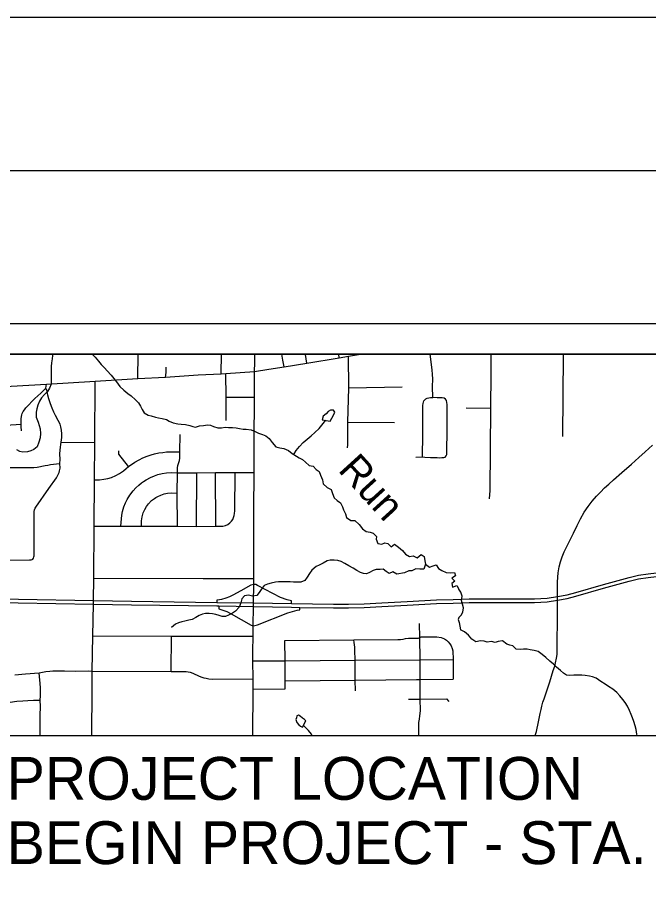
# Model space of a CAD drawing. Extents: x 0 to 34, y -5 to 22.
# Drawn here: x 5.836 to 7.898, y 19.168 to 22 of the extents above; entities that cross this region are included whole.
import ezdxf

# ---------------------------------------------------------------- set-up
doc = ezdxf.new("R2010")
doc.units = 0
for name, color, linetype in [('GM_X_City_Street', 7, 'Continuous'), ('GM_X_County_Road', 7, 'Continuous'), ('GM_X_Interchange_Ramps', 7, 'Continuous'), ('GM_X_Interstate_Route', 7, 'Continuous'), ('GM_X_Minor_Lake', 7, 'Continuous'), ('GM_X_Minor_River', 7, 'Continuous'), ('GM_X_Minor_River_Text', 7, 'Continuous'), ('GM_X_State_Route', 7, 'Continuous'), ('GM_X_US_Route', 7, 'Continuous'), ('SC_Scratch2', 7, 'Continuous'), ('SH_Border', 7, 'Continuous'), ('SH_Cut_Line', 7, 'Continuous'), ('SH_Data', 7, 'Continuous'), ('SH_Text', 7, 'Continuous')]:
    doc.layers.add(name, color=color, linetype=linetype)

msp = doc.modelspace()

# ---------------------------------------------------------------- linework, layer by layer
at = {"layer": 'GM_X_City_Street'}
for p, q in [((6.2296, 20.8205), (6.2299, 20.9)), ((6.5009, 20.8363), (6.5026, 20.9)), ((6.8873, 20.8885), (6.8858, 20.9)), ((6.918, 20.7901), (7.093, 20.7932)), ((6.5182, 20.7598), (6.6101, 20.7598)), ((7.3021, 20.7251), (7.3821, 20.7236)), ((6.9156, 20.6784), (7.0674, 20.6772)), ((5.9792, 20.6132), (6.0887, 20.6113)), ((6.4209, 20.3378), (6.4219, 20.5131)), ((6.4839, 20.3383), (6.4832, 20.5135)), ((6.338, 19.8642), (6.339, 19.9798))]:
    msp.add_line(p, q, dxfattribs=at)
for points in [[(6.7072, 20.8588), (6.7034, 20.8804), (6.6999, 20.9)], [(6.7813, 20.8707), (6.7773, 20.8986), (6.7771, 20.9)], [(6.914, 20.5948), (6.9154, 20.6038), (6.9156, 20.6784), (6.918, 20.7901), (6.9175, 20.8934)], [(7.1925, 20.7586), (7.1922, 20.7949), (7.1927, 20.8188), (7.192, 20.8354), (7.191, 20.8479), (7.1863, 20.8834), (7.1842, 20.9)], [(7.3781, 20.4278), (7.3798, 20.4553), (7.3821, 20.7236), (7.3833, 20.8363), (7.384, 20.9)], [(7.6171, 20.631), (7.6199, 20.8962), (7.6199, 20.9)], [(6.3192, 20.8256), (6.3203, 20.8316), (6.3214, 20.8411), (6.3219, 20.8489), (6.3222, 20.8579)], [(6.5178, 20.6838), (6.5182, 20.7598), (6.5169, 20.8369)], [(5.8495, 20.6502), (5.8483, 20.6642), (5.8478, 20.6717), (5.8481, 20.6812), (5.8481, 20.689), (5.849, 20.6968), (5.8499, 20.702), (5.8511, 20.7063), (5.8549, 20.7127), (5.8585, 20.7181), (5.8638, 20.7251), (5.8926, 20.7549), (5.912, 20.7733), (5.9287, 20.7894)], [(5.8862, 20.2308), (5.8885, 20.2343), (5.8895, 20.2381), (5.8902, 20.2419), (5.89, 20.3733), (5.89, 20.3819), (5.8904, 20.3868), (5.8914, 20.3916), (5.8942, 20.397), (5.8964, 20.4006), (5.9383, 20.4612), (5.9631, 20.4962), (5.9691, 20.5069), (5.9721, 20.5133), (5.9738, 20.5197), (5.975, 20.5277), (5.9747, 20.5434), (5.9752, 20.5566), (5.9747, 20.5744), (5.9755, 20.5872), (5.9764, 20.5964), (5.9776, 20.6047), (5.9792, 20.6132), (5.9814, 20.6279), (5.9814, 20.6402), (5.9802, 20.6518), (5.9778, 20.663), (5.975, 20.6713), (5.9691, 20.6833), (5.9598, 20.6994), (5.9549, 20.711), (5.9494, 20.7234), (5.9435, 20.7385), (5.9385, 20.7544), (5.9347, 20.7667), (5.9328, 20.779), (5.9287, 20.7894), (5.9309, 20.8026)], [(6.0784, 19.6552), (6.0804, 19.804), (6.0799, 19.8656), (6.0827, 19.9809), (6.084, 20.0843), (6.0838, 20.0963), (6.0851, 20.169), (6.0863, 20.339), (6.0879, 20.4896), (6.0887, 20.6113), (6.09, 20.8115)], [(7.1588, 20.5647), (7.1598, 20.6381), (7.1603, 20.7001), (7.1603, 20.7264), (7.16, 20.7328), (7.161, 20.7387), (7.1624, 20.7437), (7.164, 20.7482), (7.1667, 20.7516), (7.1702, 20.7546), (7.1745, 20.7567), (7.1801, 20.7579), (7.1858, 20.7586), (7.1925, 20.7586)], [(7.233, 20.5642), (7.2365, 20.5678), (7.2384, 20.5725), (7.2386, 20.5794), (7.2389, 20.5993), (7.2393, 20.6338), (7.2398, 20.7357), (7.2389, 20.7425), (7.2372, 20.7487), (7.2339, 20.753), (7.2294, 20.756), (7.2237, 20.7575), (7.2152, 20.7575), (7.2074, 20.7579), (7.1925, 20.7586)], [(5.7315, 20.6703), (5.7334, 20.6677), (5.7363, 20.6658), (5.7403, 20.6649), (5.7465, 20.6651), (5.8478, 20.6717)], [(6.3586, 20.3383), (6.3579, 20.4465), (6.3586, 20.5131), (6.3584, 20.5225), (6.3593, 20.5292), (6.3603, 20.537), (6.3619, 20.5427), (6.365, 20.5526), (6.3664, 20.5604), (6.3667, 20.5675), (6.3669, 20.5813), (6.3679, 20.6376)], [(7.5274, 19.6552), (7.5311, 19.6683), (7.5382, 19.6994), (7.5434, 19.7268), (7.5465, 19.7399), (7.5489, 19.7508), (7.5524, 19.764), (7.5562, 19.7747), (7.5752, 19.8303), (7.5865, 19.8673), (7.591, 19.881), (7.5941, 19.8928), (7.5974, 19.9073), (7.5991, 19.9196), (7.5995, 19.9336), (7.5993, 19.9568), (7.6005, 20.0347), (7.6001, 20.0968), (7.6001, 20.1092), (7.6001, 20.1568), (7.6024, 20.1865), (7.6055, 20.2061), (7.6095, 20.2223), (7.6154, 20.2388), (7.6225, 20.2545), (7.6303, 20.272), (7.6396, 20.2895), (7.6521, 20.3158), (7.6644, 20.3407), (7.6758, 20.3629), (7.6876, 20.384), (7.7, 20.4025), (7.7137, 20.4207), (7.7274, 20.4366), (7.7405, 20.4501), (7.7542, 20.4633), (7.7682, 20.4756), (7.7836, 20.4899), (7.8108, 20.5135), (7.8418, 20.5412), (7.8662, 20.563), (7.8868, 20.5815), (7.9105, 20.6028)], [(6.0879, 20.4896), (6.1036, 20.4901), (6.118, 20.4915), (6.1313, 20.4939), (6.1429, 20.4974), (6.1571, 20.5036), (6.1696, 20.5109), (6.1824, 20.5195), (6.1912, 20.5273), (6.1985, 20.5334), (6.2197, 20.548), (6.2334, 20.5555), (6.2458, 20.5619), (6.2594, 20.5666), (6.2724, 20.5711), (6.284, 20.5744), (6.2982, 20.5775), (6.3113, 20.5796), (6.3226, 20.5808), (6.3316, 20.5815), (6.3423, 20.5817), (6.3669, 20.5813)], [(6.1985, 20.5334), (6.1666, 20.5739), (6.1675, 20.5846)], [(7.1373, 20.5637), (7.1588, 20.5647), (7.1671, 20.5637), (7.1851, 20.563), (7.2074, 20.5626), (7.215, 20.5621), (7.2218, 20.5623), (7.2287, 20.5628), (7.233, 20.5642)], [(5.6465, 20.4906), (5.6858, 20.4896), (5.6936, 20.4903), (5.7005, 20.4917), (5.706, 20.4934), (5.7244, 20.5031), (5.7607, 20.5235), (5.7663, 20.5266), (5.7711, 20.5282), (5.7751, 20.5287), (5.7787, 20.5292), (5.7931, 20.5296), (5.8765, 20.5299), (5.8895, 20.5301), (5.9001, 20.5314), (5.9267, 20.5365), (5.9347, 20.5372), (5.9437, 20.5398), (5.9539, 20.541), (5.9634, 20.542), (5.9747, 20.5434)], [(6.0863, 20.339), (6.1741, 20.3385), (6.2416, 20.3383), (6.3586, 20.3383), (6.4209, 20.3378), (6.4839, 20.3383), (6.4972, 20.3381), (6.5073, 20.339), (6.5154, 20.3409), (6.523, 20.3444), (6.5298, 20.3492), (6.5353, 20.3549), (6.5391, 20.3603), (6.5419, 20.3672), (6.5443, 20.3738), (6.5455, 20.3802), (6.5459, 20.3887), (6.5467, 20.5133)], [(6.1741, 20.3385), (6.1753, 20.3627), (6.1768, 20.3741), (6.1796, 20.3868), (6.1836, 20.4013), (6.1891, 20.4145), (6.1943, 20.4252), (6.2033, 20.4401), (6.2139, 20.4539), (6.2222, 20.4636), (6.2322, 20.4728), (6.2409, 20.4799), (6.2478, 20.4849), (6.2563, 20.4903), (6.2705, 20.4979), (6.2833, 20.5034), (6.294, 20.5069), (6.3087, 20.5107), (6.3233, 20.5126), (6.3378, 20.5138), (6.3586, 20.5131), (6.4219, 20.5131), (6.4832, 20.5135), (6.5467, 20.5133), (6.6089, 20.514)], [(6.2416, 20.3383), (6.2414, 20.3565), (6.2435, 20.3688), (6.2468, 20.3816), (6.2523, 20.3935), (6.2575, 20.4029), (6.2644, 20.4117), (6.2743, 20.4219), (6.2836, 20.4292), (6.2883, 20.4321), (6.2942, 20.4354), (6.3042, 20.4399), (6.3153, 20.4437), (6.3262, 20.4458), (6.338, 20.447), (6.3579, 20.4465)], [(5.6498, 20.2289), (5.6517, 20.2279), (5.6553, 20.2277), (5.6588, 20.2275), (5.8755, 20.2286), (5.8803, 20.2289), (5.8836, 20.2296), (5.8862, 20.2308)], [(6.0851, 20.169), (6.4425, 20.1673), (6.6081, 20.1676)], [(7.151, 19.8377), (7.1515, 19.9026), (7.1501, 19.9745), (7.1496, 20.0205)], [(6.0827, 19.9809), (6.339, 19.9798), (6.45, 19.9798), (6.6057, 19.9794)], [(6.7094, 19.9651), (6.9346, 19.9672), (7.0783, 19.9684), (7.0868, 19.9686), (7.0956, 19.97), (7.1037, 19.9715), (7.1136, 19.9724), (7.1321, 19.9726), (7.146, 19.9726), (7.1501, 19.9745), (7.1553, 19.9767), (7.2057, 19.9771), (7.2197, 19.9745), (7.2251, 19.9729), (7.2306, 19.9705), (7.2372, 19.966), (7.2427, 19.961), (7.2483, 19.9546), (7.2531, 19.9473), (7.2564, 19.9395), (7.2585, 19.9317), (7.259, 19.9037), (7.2597, 19.8393)], [(6.94, 19.8012), (6.9391, 19.8358), (6.9395, 19.9007), (6.9381, 19.9336), (6.9379, 19.943), (6.9367, 19.9509), (6.9355, 19.9591), (6.9346, 19.9672)], [(6.7105, 19.8334), (6.7103, 19.8985), (6.7094, 19.9651)], [(6.6052, 19.8985), (6.7103, 19.8985), (6.9395, 19.9007), (7.1515, 19.9026), (7.259, 19.9037)], [(5.8277, 19.8528), (5.8625, 19.8561), (5.9073, 19.8597), (5.929, 19.8635), (5.9416, 19.8654), (5.9515, 19.8658), (5.9681, 19.8658), (5.9899, 19.8661), (6.0264, 19.8649), (6.0692, 19.8658), (6.0799, 19.8656), (6.338, 19.8642), (6.3816, 19.8635), (6.3875, 19.8635), (6.3937, 19.8628), (6.4003, 19.8616), (6.4093, 19.859), (6.4299, 19.8493), (6.4382, 19.846), (6.4453, 19.8436), (6.4529, 19.8419), (6.4612, 19.8403), (6.4735, 19.8386), (6.6059, 19.8398)], [(5.9097, 19.6552), (5.9097, 19.6724), (5.9106, 19.7202), (5.911, 19.7498), (5.9099, 19.7702), (5.9113, 19.7846), (5.911, 19.7984), (5.9108, 19.8111), (5.9103, 19.8249), (5.9077, 19.8476), (5.9073, 19.8597)], [(6.6059, 19.8059), (6.7103, 19.8071), (6.7105, 19.8334), (6.9391, 19.8358), (7.1401, 19.8379), (7.151, 19.8377), (7.2597, 19.8393)], [(7.1469, 19.6552), (7.1468, 19.6717), (7.147, 19.6899), (7.1475, 19.6977), (7.1489, 19.7079), (7.1503, 19.7188), (7.1517, 19.7264), (7.1527, 19.7368), (7.152, 19.7735), (7.151, 19.8377)], [(5.5859, 19.755), (5.6515, 19.755), (5.7356, 19.7571), (5.7801, 19.7612), (5.7986, 19.7631), (5.8125, 19.7642), (5.8341, 19.7671), (5.8537, 19.7683), (5.8696, 19.7695), (5.8888, 19.7699), (5.9099, 19.7702)], [(7.1131, 19.7735), (7.152, 19.7735), (7.2379, 19.7744), (7.2455, 19.7659)]]:
    msp.add_lwpolyline(points, dxfattribs=at)
at = {"layer": 'GM_X_County_Road'}
for p, q in [((6.6108, 20.8437), (6.6109, 20.8733)), ((6.6109, 20.8733), (6.611, 20.9)), ((6.6081, 20.1775), (6.6083, 20.2765))]:
    msp.add_line(p, q, dxfattribs=at)
for points in [[(6.6089, 20.514), (6.6094, 20.6132), (6.6101, 20.7598), (6.6108, 20.8437)], [(6.6083, 20.2765), (6.6085, 20.3904), (6.6089, 20.514)], [(6.6063, 20.0043), (6.6065, 20.0126), (6.607, 20.0764), (6.6071, 20.0879), (6.6076, 20.1484), (6.6081, 20.1676), (6.6081, 20.1775)], [(6.6054, 19.9289), (6.6057, 19.9794), (6.6063, 20.0043)], [(6.6051, 19.6552), (6.6059, 19.8059), (6.6059, 19.8398), (6.6052, 19.8985), (6.6054, 19.9289)]]:
    msp.add_lwpolyline(points, dxfattribs=at)
at = {"layer": 'GM_X_Interchange_Ramps'}
for points in [[(6.6076, 20.1484), (6.5984, 20.1458), (6.5658, 20.1274), (6.5397, 20.1133), (6.5291, 20.1079), (6.517, 20.1036), (6.5024, 20.0993), (6.4898, 20.097), (6.4873, 20.0966), (6.4872, 20.0898)], [(6.7311, 20.086), (6.7314, 20.0947), (6.7169, 20.0981), (6.6948, 20.1059), (6.6205, 20.1443), (6.6142, 20.1476), (6.6076, 20.1484)], [(6.4934, 20.078), (6.4933, 20.0684), (6.5066, 20.0642), (6.5194, 20.0595), (6.5338, 20.0524), (6.599, 20.0149), (6.6065, 20.0126)], [(6.6065, 20.0126), (6.6119, 20.0143), (6.6196, 20.0159), (6.7189, 20.0553), (6.7346, 20.06), (6.75, 20.0638), (6.7584, 20.065), (6.7586, 20.0735)]]:
    msp.add_lwpolyline(points, dxfattribs=at)
at = {"layer": 'GM_X_Interstate_Route'}
for points in [[(5.5366, 20.105), (5.8389, 20.1002), (6.0838, 20.0963), (6.2087, 20.0942), (6.4872, 20.0898), (6.6071, 20.0879), (6.7311, 20.086), (6.8679, 20.0836), (6.9177, 20.0841), (6.9687, 20.0852), (7.0264, 20.0881), (7.1093, 20.0925), (7.2048, 20.0978), (7.2598, 20.0996), (7.3114, 20.1018), (7.3512, 20.1015), (7.4172, 20.1012), (7.4791, 20.101), (7.5249, 20.1012), (7.5659, 20.1039), (7.6001, 20.1092), (7.6315, 20.1146), (7.6604, 20.1223), (7.7504, 20.1483), (7.7981, 20.1612), (7.8341, 20.1707), (7.8651, 20.1784), (7.8965, 20.1825), (7.9236, 20.186)], [(6.7586, 20.0735), (6.8679, 20.0716), (6.9176, 20.0721), (6.9687, 20.0731), (7.0263, 20.076), (7.1092, 20.0805), (7.2048, 20.0858), (7.2598, 20.0876), (7.3113, 20.0898), (7.3511, 20.0895), (7.4172, 20.0892), (7.479, 20.0889), (7.5248, 20.0892), (7.5659, 20.0918), (7.6001, 20.0968), (7.6314, 20.1026), (7.6604, 20.1102), (7.7504, 20.1363), (7.798, 20.1492), (7.8341, 20.1587), (7.865, 20.1663), (7.8964, 20.1705), (7.9235, 20.1739), (7.954, 20.1757)], [(5.3921, 20.0954), (5.5364, 20.093), (5.8387, 20.0883), (6.084, 20.0843), (6.2084, 20.0822), (6.4872, 20.0779), (6.4934, 20.078)], [(6.4934, 20.078), (6.607, 20.0764), (6.7308, 20.0742), (6.7586, 20.0735)]]:
    msp.add_lwpolyline(points, dxfattribs=at)
at = {"layer": 'GM_X_Minor_Lake'}
for points in [[(6.8573, 20.6819), (6.8686, 20.701), (6.8724, 20.7109), (6.8685, 20.717), (6.8587, 20.7173), (6.8507, 20.713), (6.8443, 20.705), (6.8349, 20.6981), (6.8319, 20.686)], [(6.8319, 20.686), (6.8573, 20.6819)], [(6.7784, 19.7029), (6.7739, 19.7078), (6.7674, 19.7112), (6.7598, 19.7184), (6.7545, 19.7214), (6.7488, 19.7187), (6.7473, 19.713), (6.7458, 19.7069), (6.7485, 19.697), (6.755, 19.6895), (6.7611, 19.6857), (6.7675, 19.6827)], [(6.7675, 19.6827), (6.7784, 19.7029)]]:
    msp.add_lwpolyline(points, dxfattribs=at)
at = {"layer": 'GM_X_Minor_River'}
for points in [[(5.9504, 20.9), (5.9499, 20.896), (5.9488, 20.885), (5.9474, 20.8717), (5.9463, 20.8603), (5.946, 20.8473), (5.9456, 20.8378), (5.9461, 20.8268), (5.9465, 20.815), (5.9458, 20.8025), (5.941, 20.7891), (5.9338, 20.7788), (5.924, 20.7681), (5.9142, 20.7578), (5.9082, 20.7471), (5.9026, 20.7338), (5.8992, 20.7212), (5.8974, 20.7113), (5.8975, 20.6942), (5.9036, 20.6779), (5.9071, 20.6677), (5.9098, 20.6559), (5.9117, 20.6407), (5.9099, 20.6266), (5.9054, 20.6125), (5.8998, 20.5981), (5.8896, 20.5889), (5.8794, 20.5846), (5.8692, 20.5815), (5.8533, 20.5799), (5.8434, 20.5822), (5.8339, 20.5882)], [(6.0804, 20.9), (6.0894, 20.8907), (6.1009, 20.8775), (6.1096, 20.8669)], [(6.1096, 20.8669), (6.1199, 20.8552), (6.1295, 20.8453), (6.142, 20.8321), (6.1512, 20.8211), (6.1592, 20.8094), (6.1703, 20.7946), (6.1832, 20.7829), (6.1969, 20.772), (6.2072, 20.7637), (6.2213, 20.7516), (6.2312, 20.7414), (6.2377, 20.7304), (6.2434, 20.7194), (6.2495, 20.7088), (6.2632, 20.7005), (6.2727, 20.6983), (6.2864, 20.6946), (6.2966, 20.6927), (6.3084, 20.6905), (6.3224, 20.6864), (6.3319, 20.6819), (6.3441, 20.6759), (6.3597, 20.673), (6.371, 20.6715), (6.3854, 20.6701), (6.3987, 20.6671), (6.4086, 20.6637), (6.4181, 20.6623), (6.4306, 20.6661), (6.4438, 20.6677), (6.4567, 20.6693), (6.4662, 20.6686), (6.4768, 20.6638), (6.4905, 20.6597), (6.503, 20.6593), (6.5148, 20.6613), (6.525, 20.661), (6.5379, 20.6607), (6.5504, 20.6592), (6.5614, 20.657), (6.5732, 20.6556), (6.583, 20.6549), (6.599, 20.6527), (6.6122, 20.6478), (6.6233, 20.6426), (6.6362, 20.6381), (6.6468, 20.6332), (6.6578, 20.6253), (6.6685, 20.6113), (6.6796, 20.5976), (6.6929, 20.5939), (6.7065, 20.5925), (6.7214, 20.5853), (6.7339, 20.5759), (6.7472, 20.5672), (6.7567, 20.5612), (6.7666, 20.5567), (6.7773, 20.548), (6.7887, 20.5367), (6.802, 20.5345), (6.8119, 20.5235), (6.8218, 20.5171), (6.8256, 20.505), (6.8321, 20.4902), (6.8345, 20.4765), (6.8478, 20.4652), (6.8603, 20.458), (6.865, 20.4451), (6.8703, 20.4315), (6.8799, 20.4224), (6.8916, 20.4149), (6.8974, 20.402), (6.9012, 20.3921), (6.9081, 20.3785), (6.9112, 20.3671), (6.9245, 20.3573), (6.9378, 20.357), (6.9519, 20.3441), (6.963, 20.3301), (6.9748, 20.3211), (6.988, 20.3192), (6.9983, 20.3155), (7.0086, 20.3053), (7.0082, 20.2958), (7.0132, 20.2825), (7.0261, 20.2803), (7.036, 20.2842), (7.0455, 20.2816), (7.0565, 20.2706), (7.0682, 20.2802), (7.0811, 20.27), (7.0933, 20.259), (7.104, 20.2469), (7.1166, 20.239), (7.1287, 20.2421), (7.1412, 20.235), (7.1552, 20.2457), (7.1651, 20.2397), (7.167, 20.2256), (7.1694, 20.2142)], [(6.7386, 20.5728), (6.7468, 20.5851), (6.7577, 20.5985), (6.7697, 20.6115), (6.7822, 20.6226), (6.7958, 20.634), (6.8079, 20.644), (6.8218, 20.6578), (6.843, 20.6842)], [(7.1694, 20.2142), (7.1638, 20.1986), (7.1505, 20.1978), (7.1376, 20.1992), (7.1244, 20.1927), (7.1149, 20.1922), (7.1005, 20.1865), (7.0748, 20.1817), (7.0626, 20.1897), (7.0501, 20.1839), (7.0402, 20.191), (7.0307, 20.1978), (7.0209, 20.1974), (7.008, 20.1969), (6.9981, 20.1938), (6.9857, 20.1873), (6.9758, 20.1831), (6.966, 20.1838), (6.9565, 20.1875), (6.9443, 20.1939), (6.9329, 20.2011), (6.9184, 20.209), (6.9059, 20.2169), (6.893, 20.2229), (6.8823, 20.2263), (6.871, 20.2277), (6.8577, 20.2276), (6.8475, 20.2257), (6.835, 20.2176), (6.8214, 20.2115), (6.8116, 20.2068), (6.798, 20.1954), (6.7904, 20.1835), (6.7822, 20.1717), (6.7746, 20.161), (6.7614, 20.1556), (6.7485, 20.1552), (6.7379, 20.1562), (6.7265, 20.1565), (6.7167, 20.1565), (6.7, 20.1572), (6.689, 20.1567), (6.6791, 20.1555), (6.6644, 20.1528), (6.653, 20.1497), (6.6424, 20.1447), (6.6326, 20.1321), (6.6251, 20.1221), (6.6176, 20.1118), (6.6039, 20.1095), (6.591, 20.1136), (6.5781, 20.1116), (6.5691, 20.1013), (6.5654, 20.0883), (6.5601, 20.0739), (6.5485, 20.0605), (6.5352, 20.0524), (6.5156, 20.0439), (6.5049, 20.0435), (6.4947, 20.0469), (6.4844, 20.0506), (6.4734, 20.0524), (6.4621, 20.0535), (6.4507, 20.0531), (6.4401, 20.0511), (6.4295, 20.0465), (6.4189, 20.0407), (6.4064, 20.0342), (6.3962, 20.0311), (6.383, 20.0283), (6.3724, 20.0264), (6.3625, 20.0229), (6.3519, 20.0183), (6.3391, 20.0076)], [(7.1694, 20.2142), (7.1815, 20.2052), (7.194, 20.2094), (7.2039, 20.2118), (7.2115, 20.2008), (7.2225, 20.194), (7.2362, 20.1872), (7.2514, 20.1866), (7.2635, 20.1878), (7.2666, 20.1768), (7.2549, 20.1691), (7.2652, 20.1589), (7.2553, 20.1516), (7.2577, 20.1391), (7.2713, 20.1445), (7.2775, 20.133)], [(7.2851, 20.048), (7.2911, 20.0576), (7.2936, 20.0721), (7.2893, 20.0842), (7.2869, 20.0963), (7.2891, 20.1096), (7.2848, 20.1232), (7.2775, 20.133)], [(7.2851, 20.048), (7.2783, 20.0405), (7.276, 20.0334), (7.2791, 20.0245), (7.2834, 19.9998)], [(7.8603, 19.6552), (7.8596, 19.6597), (7.8568, 19.6741), (7.8536, 19.687), (7.8497, 19.7002), (7.8451, 19.7127), (7.8412, 19.7237), (7.8353, 19.7369), (7.8284, 19.7505), (7.8211, 19.763), (7.8134, 19.7728), (7.8042, 19.7848), (7.7935, 19.7953), (7.7805, 19.8066), (7.7664, 19.8155), (7.7554, 19.8226), (7.7416, 19.8316), (7.7264, 19.8417), (7.7142, 19.8461), (7.7044, 19.8487), (7.6907, 19.8512), (7.6801, 19.8522), (7.6661, 19.852), (7.6536, 19.8515), (7.6407, 19.8514), (7.6301, 19.852), (7.6195, 19.8584), (7.6095, 19.867), (7.5965, 19.8786), (7.5866, 19.8876), (7.5755, 19.8978), (7.5622, 19.9098), (7.5499, 19.9191), (7.5366, 19.9289), (7.5244, 19.9329), (7.5108, 19.935), (7.5009, 19.9368), (7.4888, 19.9371), (7.479, 19.9358), (7.4653, 19.9368), (7.4539, 19.9481), (7.444, 19.9503), (7.4345, 19.9536), (7.42, 19.9637), (7.406, 19.962), (7.3962, 19.9585), (7.3844, 19.9621), (7.3701, 19.9601), (7.3606, 19.9626), (7.3481, 19.9644), (7.3334, 19.9608), (7.3204, 19.9698), (7.3093, 19.983), (7.2963, 19.9935), (7.2834, 19.9998)], [(6.799, 19.6552), (6.7965, 19.6589), (6.7869, 19.6714), (6.7704, 19.688)]]:
    msp.add_lwpolyline(points, dxfattribs=at)
at = {"layer": 'GM_X_State_Route'}
for points in [[(6.6108, 20.8437), (6.6572, 20.8512), (6.7072, 20.8588), (6.7813, 20.8707), (6.8873, 20.8885), (6.9175, 20.8934), (6.9567, 20.9)], [(5.4578, 20.775), (5.5385, 20.7794), (5.6081, 20.7844), (5.6468, 20.7866), (5.7269, 20.7908), (5.8158, 20.7961), (5.9309, 20.8026), (6.09, 20.8115), (6.2296, 20.8205), (6.3192, 20.8256), (6.4266, 20.8325), (6.5009, 20.8363), (6.5169, 20.8369), (6.6108, 20.8437)]]:
    msp.add_lwpolyline(points, dxfattribs=at)
at = {"layer": 'GM_X_US_Route'}
for points in [[(5.8013, 16.5622), (5.8852, 16.5633), (6.0263, 16.5646), (6.0369, 16.5647), (6.1314, 16.5662), (6.137, 16.5663), (6.3903, 16.5692), (6.5815, 16.5715), (6.8205, 16.573), (6.884, 16.5737), (7.1656, 16.577), (7.5561, 16.5815), (7.6886, 16.5826), (7.9095, 16.5845), (8.2655, 16.5864), (8.5829, 16.5932), (8.9, 16.5981), (8.9, 20.9), (4.0002, 20.9)], [(6.7586, 20.0735), (6.8679, 20.0716), (6.9176, 20.0721), (6.9687, 20.0731), (7.0263, 20.076), (7.1092, 20.0805), (7.2048, 20.0858), (7.2598, 20.0876), (7.3113, 20.0898), (7.3511, 20.0895), (7.4172, 20.0892), (7.479, 20.0889), (7.5248, 20.0892), (7.5659, 20.0918), (7.6001, 20.0968), (7.6314, 20.1026), (7.6604, 20.1102), (7.7504, 20.1363), (7.798, 20.1492), (7.8341, 20.1587), (7.865, 20.1663), (7.8964, 20.1705), (7.9235, 20.1739), (7.954, 20.1757)], [(5.3921, 20.0954), (5.5364, 20.093), (5.8387, 20.0883), (6.084, 20.0843), (6.2084, 20.0822), (6.4872, 20.0779), (6.4934, 20.078)], [(6.4934, 20.078), (6.607, 20.0764), (6.7308, 20.0742), (6.7586, 20.0735)]]:
    msp.add_lwpolyline(points, dxfattribs=at)
at = {"layer": 'SC_Scratch2'}
msp.add_lwpolyline([(8.0942, 19.1372), (8.0967, 19.418), (8.1279, 19.4215), (8.4144, 19.4254), (8.4988, 19.4237), (8.4969, 19.3237), (8.6351, 19.3269), (8.6328, 19.4064), (8.6389, 19.6762), (8.6374, 19.7404), (8.6419, 19.8009), (8.6394, 19.8511), (8.6633, 19.8506), (8.772, 19.8486), (8.8842, 19.8448), (8.9, 19.8443), (8.9, 20.9), (4.0005, 20.9)], dxfattribs=at)
at = {"layer": 'SH_Border'}
msp.add_lwpolyline([(1.5, 21.5), (33.5, 21.5), (33.5, 0.5), (1.5, 0.5)], close=True, dxfattribs=at)
at = {"layer": 'SH_Cut_Line'}
msp.add_lwpolyline([(0, 0), (34, 0), (34, 22), (0, 22)], close=True, dxfattribs=at)
msp.add_lwpolyline([(8.9, 14.1), (8.9, 20.9), (4.0002, 20.9)], dxfattribs=at)
at = {"layer": 'SH_Data'}
for p, q in [((2, 21), (9, 21)), ((2.1, 20.9), (8.9, 20.9))]:
    msp.add_line(p, q, dxfattribs=at)
at = {"layer": 'SH_Text'}
msp.add_lwpolyline([(5.7495, 19.6552), (8.7592, 19.6552), (8.7592, 18.9062), (5.7495, 18.9062)], close=True, dxfattribs=at)

# ---------------------------------------------------------------- texts
at = {"layer": 'GM_X_Minor_River_Text'}
msp.add_text('Run', height=0.09474, rotation=312.266, dxfattribs=at).set_placement((6.8804, 20.5204))
at = {"layer": 'SH_Text'}
for s, p in [('PROJECT LOCATION', (5.8006, 19.445)), ('BEGIN PROJECT - STA. 502+05.25', (5.8006, 19.235))]:
    msp.add_text(s, height=0.14, dxfattribs=at).set_placement(p)

doc.saveas('drawing.dxf')
